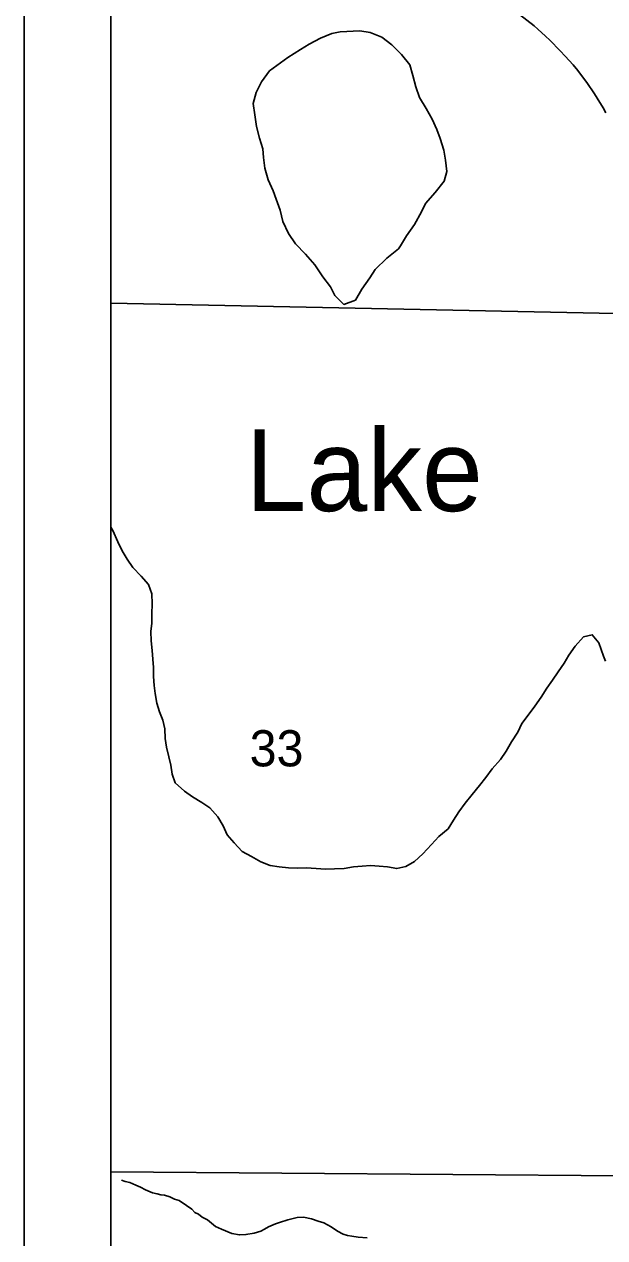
# Model space of a CAD drawing. Extents: x 0 to 34, y 0 to 22.
# Drawn here: x 18.5 to 19.172, y 16.628 to 18.033 of the extents above; entities that cross this region are included whole.
import ezdxf

# ---------------------------------------------------------------- set-up
doc = ezdxf.new("R2010")
doc.units = 0
for name, color, linetype in [('GM_X_Corporation', 7, 'Continuous'), ('GM_X_Major_Lake', 7, 'Continuous'), ('GM_X_Major_Lake_Text', 7, 'Continuous'), ('GM_X_Minor_River', 7, 'Continuous'), ('GM_X_Section_Text', 7, 'Continuous'), ('GM_X_US_Route', 7, 'Continuous'), ('SH_Data', 7, 'Continuous')]:
    doc.layers.add(name, color=color, linetype=linetype)

msp = doc.modelspace()

# ---------------------------------------------------------------- linework, layer by layer
at = {"layer": 'GM_X_Corporation'}
for points in [[(18.6, 19.2331), (18.6, 14.6606), (18.9216, 14.6592), (19.4007, 14.6554), (19.8855, 14.6528), (20.2016, 14.6512), (20.203, 14.81), (20.1987, 15.2691), (20.2208, 16.9558), (20.2471, 18.8539), (20.254, 19.2058), (20.065, 19.208), (18.9898, 19.2261)], [(18.6, 18.7129), (18.6, 17.7098), (19.222, 17.6968), (19.241, 18.7106)], [(18.6, 17.7098), (18.6, 16.7037), (19.1937, 16.6992), (19.222, 17.6968)], [(18.6, 16.7037), (18.6, 15.673), (19.1743, 15.6658), (19.1937, 16.6992)]]:
    msp.add_lwpolyline(points, close=True, dxfattribs=at)
at = {"layer": 'GM_X_Major_Lake'}
for points in [[(18.9329, 17.7725), (18.9355, 17.776), (18.9422, 17.7878), (18.9515, 17.8008), (18.9597, 17.8153), (18.9642, 17.8252), (18.9754, 17.8378), (18.9859, 17.8508), (18.9888, 17.8622), (18.9875, 17.8751), (18.9855, 17.8868), (18.9812, 17.9004), (18.9773, 17.9106), (18.9719, 17.9227), (18.965, 17.9352), (18.9573, 17.9476), (18.953, 17.9601), (18.9495, 17.9733), (18.9463, 17.9858), (18.9367, 17.9974), (18.9252, 18.0087), (18.9138, 18.0177), (18.9001, 18.0232), (18.8883, 18.025), (18.8656, 18.024), (18.8558, 18.022), (18.8426, 18.0166), (18.8298, 18.0097), (18.8196, 18.0035), (18.8049, 17.9942), (18.7839, 17.9785)], [(18.7839, 17.9785), (18.7745, 17.9659), (18.7682, 17.9537), (18.7649, 17.9407), (18.7669, 17.9279), (18.7689, 17.9142), (18.7721, 17.9006), (18.776, 17.8882), (18.7769, 17.8783), (18.7785, 17.8658), (18.7821, 17.8526), (18.7882, 17.8397), (18.7914, 17.8299), (18.796, 17.8174), (18.7992, 17.8042), (18.8058, 17.7902), (18.8138, 17.7782), (18.8253, 17.7665), (18.8361, 17.7541), (18.8453, 17.7402), (18.8545, 17.7285), (18.8595, 17.7187), (18.8698, 17.7082), (18.8831, 17.7133), (18.8905, 17.7259), (18.8999, 17.7388), (18.9062, 17.7488), (18.9197, 17.7618), (18.9329, 17.7725)], [(18.6, 17.4504), (18.6025, 17.4464), (18.6082, 17.4332), (18.6131, 17.4229), (18.6192, 17.4131), (18.6256, 17.4036), (18.6351, 17.3937), (18.6438, 17.3839), (18.6476, 17.3729), (18.648, 17.3615), (18.6476, 17.3501), (18.6476, 17.3391), (18.6465, 17.3296), (18.6469, 17.3186), (18.6481, 17.3076), (18.6488, 17.2974), (18.6496, 17.2879), (18.6496, 17.2773), (18.6504, 17.267), (18.6515, 17.2576), (18.6534, 17.2466), (18.6564, 17.2363), (18.6602, 17.2268), (18.6625, 17.2166), (18.6629, 17.2056), (18.6644, 17.1957), (18.6671, 17.1844), (18.6697, 17.1745), (18.6712, 17.1643), (18.6747, 17.1544), (18.6853, 17.1446), (18.6947, 17.1381), (18.7053, 17.1313)], [(18.7053, 17.1313), (18.7148, 17.1252), (18.7239, 17.115), (18.7303, 17.1044), (18.7349, 17.0942), (18.7428, 17.0847), (18.7523, 17.0748), (18.7629, 17.0691), (18.7739, 17.0627), (18.7845, 17.0586), (18.7951, 17.057), (18.8057, 17.0559), (18.8159, 17.0556), (18.8261, 17.0559), (18.8379, 17.0552), (18.8485, 17.0541), (18.8591, 17.0545), (18.8701, 17.0552), (18.881, 17.0568), (18.8909, 17.0579), (18.9007, 17.0587), (18.9106, 17.0576), (18.9204, 17.0568), (18.931, 17.0549), (18.9416, 17.0572), (18.9514, 17.0633), (18.9613, 17.072), (18.9711, 17.0827), (18.9798, 17.0922), (18.9904, 17.1009), (18.9968, 17.1112), (19.0029, 17.1207), (19.0101, 17.1305), (19.0184, 17.1408), (19.0267, 17.151), (19.0343, 17.1605), (19.0415, 17.1704), (19.0509, 17.1814), (19.0577, 17.1909), (19.0638, 17.2019), (19.071, 17.2129), (19.0759, 17.2228), (19.0831, 17.2327), (19.091, 17.2429), (19.0982, 17.2536), (19.1046, 17.2638), (19.1114, 17.2733), (19.1178, 17.2828), (19.1247, 17.2927), (19.1303, 17.3022), (19.1375, 17.3124), (19.1473, 17.3234), (19.1572, 17.3257), (19.1648, 17.3162), (19.1703, 17.3009)], [(19.1703, 17.3009), (19.1724, 17.295)]]:
    msp.add_lwpolyline(points, dxfattribs=at)
at = {"layer": 'GM_X_Minor_River'}
msp.add_lwpolyline([(18.8966, 16.6272), (18.8863, 16.6282), (18.8791, 16.6293), (18.8742, 16.63), (18.8689, 16.6318), (18.8624, 16.6351), (18.8551, 16.6403), (18.8467, 16.6448), (18.8402, 16.6466), (18.8323, 16.6495), (18.8231, 16.6513), (18.8156, 16.6508), (18.805, 16.6483), (18.7952, 16.6451), (18.7907, 16.6435), (18.7828, 16.64), (18.7779, 16.6373), (18.7738, 16.6353), (18.7659, 16.6329), (18.7564, 16.6312), (18.7489, 16.6307), (18.7401, 16.6325), (18.7283, 16.6373), (18.7211, 16.6406), (18.7119, 16.6481), (18.7058, 16.6514), (18.7016, 16.6548), (18.6974, 16.6566), (18.6939, 16.6607), (18.6878, 16.6648), (18.6794, 16.6708), (18.6737, 16.6722), (18.6684, 16.6748), (18.6623, 16.6766), (18.6581, 16.6773), (18.6539, 16.6784), (18.6482, 16.6795), (18.6402, 16.6828), (18.6345, 16.6861), (18.6292, 16.6883), (18.6223, 16.6916), (18.6166, 16.6927), (18.6124, 16.6941)], dxfattribs=at)
at = {"layer": 'GM_X_US_Route'}
msp.add_lwpolyline([(19.0732, 18.0437), (19.0899, 18.0306), (19.0941, 18.0268), (19.103, 18.0189), (19.1081, 18.014), (19.1202, 18.0019), (19.1261, 17.9957), (19.1353, 17.9855), (19.1406, 17.9789), (19.1459, 17.9718), (19.1508, 17.9651), (19.16, 17.9519), (19.163, 17.9472), (19.1697, 17.9359), (19.1731, 17.9299)], dxfattribs=at)
at = {"layer": 'SH_Data'}
for points in [[(18.5, 20.5), (25.5, 20.5), (25.5, 13.5), (18.5, 13.5)], [(18.6, 20.4), (25.4, 20.4), (25.4, 13.6), (18.6, 13.6)]]:
    msp.add_lwpolyline(points, close=True, dxfattribs=at)

# ---------------------------------------------------------------- texts
at = {"layer": 'GM_X_Major_Lake_Text'}
msp.add_text('Lake', height=0.09469, rotation=359.9678, dxfattribs=at).set_placement((18.7561, 17.469))
at = {"layer": 'GM_X_Section_Text'}
msp.add_text('33', height=0.04186, rotation=0, dxfattribs=at).set_placement((18.7608, 17.1733))

doc.saveas('drawing.dxf')
